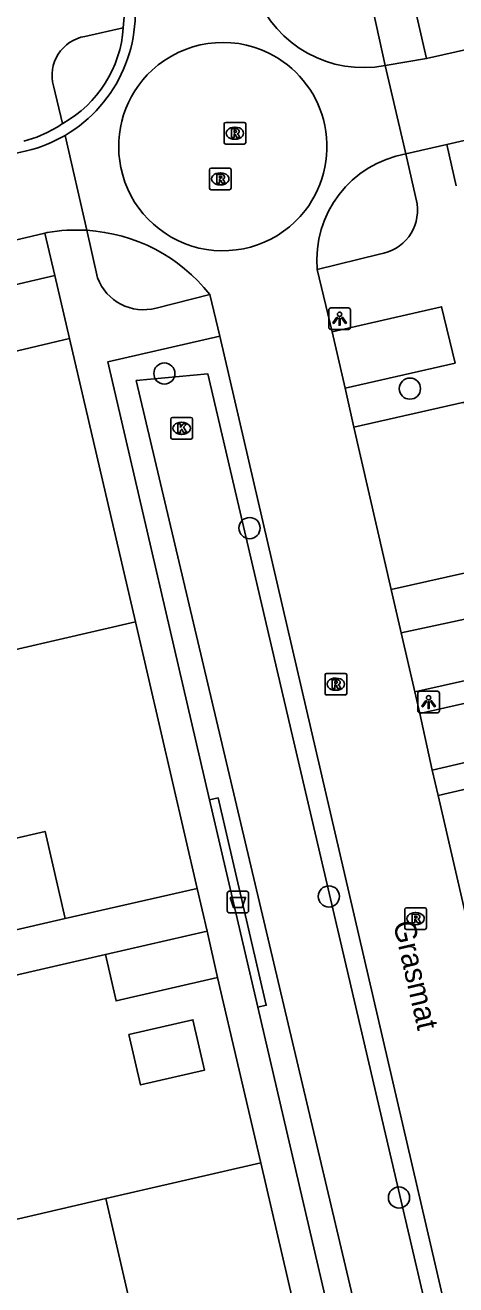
# Model space of a CAD drawing. Extents: x 156414 to 157775, y 382335 to 383765.
# Drawn here: x 156925.8 to 156945.6, y 382800.7 to 382858.9 of the extents above; entities that cross this region are included whole.
import ezdxf

# ---------------------------------------------------------------- set-up
doc = ezdxf.new("R2010")
doc.units = 0
for name, color, linetype in [('IMGEO_Afvalbak', 7, 'Continuous'), ('IMGEO_Boom', 7, 'Continuous'), ('IMGEO_Greppel_droge_sloot', 7, 'Continuous'), ('IMGEO_Haag', 7, 'Continuous'), ('IMGEO_Kolk', 7, 'Continuous'), ('IMGEO_Lichtpunt', 7, 'Continuous'), ('IMGEO_Muur', 7, 'Continuous'), ('IMGEO_Openbare_ruimte_label', 7, 'Continuous'), ('IMGEO_Pand', 7, 'Continuous'), ('IMGEO_Rijbaan_lokaal_gesloten', 7, 'Continuous'), ('IMGEO_Rijbaan_lokaal_open', 7, 'Continuous'), ('IMGEO_Rioolput', 7, 'Continuous'), ('IMGEO_Voetpad_open', 7, 'Continuous')]:
    doc.layers.add(name, color=color, linetype=linetype)

msp = doc.modelspace()

# ---------------------------------------------------------------- linework, layer by layer
at = {"layer": 'IMGEO_Afvalbak'}
for p, q in [((156935.078, 382817.947), (156935.078, 382818.747)), ((156935.078, 382818.747), (156935.078, 382817.947)), ((156935.178, 382818.847), (156935.968, 382818.847)), ((156935.968, 382818.847), (156935.178, 382818.847)), ((156936.068, 382818.747), (156936.068, 382817.947)), ((156936.068, 382817.947), (156936.068, 382818.747)), ((156935.968, 382817.847), (156935.178, 382817.847)), ((156935.178, 382817.847), (156935.968, 382817.847))]:
    msp.add_line(p, q, dxfattribs=at)
msp.add_lwpolyline([(156935.221, 382818.561), (156935.925, 382818.561), (156935.776, 382818.091), (156935.37, 382818.091), (156935.221, 382818.561)], dxfattribs=at)
for centre, start, end in [((156935.178, 382818.747), 90, 180), ((156935.178, 382818.747), 90, 180), ((156935.968, 382818.747), 0, 90), ((156935.968, 382818.747), 360, 90), ((156935.178, 382817.947), 180, 270), ((156935.178, 382817.947), 180, 270), ((156935.968, 382817.947), 270, 0), ((156935.968, 382817.947), 270, 0)]:
    msp.add_arc(centre, 0.1, start, end, dxfattribs=at)
at = {"layer": 'IMGEO_Boom'}
for centre in [(156932.178, 382842.779), (156943.519, 382842.081), (156936.113, 382835.634), (156939.776, 382818.609), (156943.014, 382804.691)]:
    msp.add_circle(centre, 0.489, dxfattribs=at)
at = {"layer": 'IMGEO_Greppel_droge_sloot'}
msp.add_lwpolyline([(156941.405, 382797.86), (156944.492, 382798.653), (156934.181, 382842.771), (156930.876, 382842.454), (156941.405, 382797.86)], dxfattribs=at)
at = {"layer": 'IMGEO_Haag'}
msp.add_lwpolyline([(156934.267, 382823.071), (156934.658, 382823.159), (156936.883, 382813.583), (156936.492, 382813.495)], dxfattribs=at)
at = {"layer": 'IMGEO_Kolk'}
for p, q in [((156932.55, 382840.748), (156933.402, 382840.748)), ((156932.475, 382839.822), (156932.475, 382840.674)), ((156932.963, 382840.528), (156932.988, 382840.528)), ((156933.476, 382840.674), (156933.476, 382839.822)), ((156933.402, 382839.748), (156932.55, 382839.748)), ((156932.986, 382839.968), (156932.961, 382839.968))]:
    msp.add_line(p, q, dxfattribs=at)
for points in [[(156932.55, 382840.748), (156933.402, 382840.748)], [(156932.475, 382839.822), (156932.475, 382840.674)], [(156932.796, 382840.448), (156932.919, 382840.448), (156932.919, 382840.297), (156933.049, 382840.448), (156933.213, 382840.448), (156933.067, 382840.297), (156933.22, 382840.048), (156933.068, 382840.048), (156932.983, 382840.212), (156932.919, 382840.145), (156932.919, 382840.048), (156932.796, 382840.048), (156932.796, 382840.448)], [(156933.476, 382840.674), (156933.476, 382839.822)], [(156933.402, 382839.748), (156932.55, 382839.748)]]:
    msp.add_lwpolyline(points, dxfattribs=at)
for centre, start, end in [((156932.552, 382840.672), 91.55205, 178.44795), ((156932.552, 382840.672), 91.55205, 178.44795), ((156933.4, 382840.672), 1.55205, 88.44795), ((156933.4, 382840.672), 1.55205, 88.44795), ((156932.552, 382839.824), 181.55205, 268.44795), ((156932.552, 382839.824), 181.55205, 268.44795), ((156933.4, 382839.824), 271.55205, 358.44795), ((156933.4, 382839.824), 271.55205, 358.44795)]:
    msp.add_arc(centre, 0.0765, start, end, dxfattribs=at)
for centre, major_axis, ratio, start_param, end_param in [((156932.962, 382840.248), (-0.387, 0.002), 0.722429, 4.712389, 7.853982), ((156932.987, 382840.248), (-0.39, 0.002), 0.717154, 1.570796, 4.712389)]:
    msp.add_ellipse(centre, major_axis=major_axis, ratio=ratio, start_param=start_param, end_param=end_param, dxfattribs=at)
at = {"layer": 'IMGEO_Lichtpunt'}
for p, q in [((156939.774, 382845.718), (156939.774, 382844.911)), ((156939.774, 382845.718), (156939.774, 382844.911)), ((156940.676, 382845.813), (156939.868, 382845.813)), ((156940.676, 382845.813), (156939.868, 382845.813)), ((156940.77, 382844.911), (156940.77, 382845.718)), ((156940.77, 382844.911), (156940.77, 382845.718)), ((156939.868, 382844.817), (156940.676, 382844.817)), ((156939.868, 382844.817), (156940.676, 382844.817)), ((156943.884, 382827.995), (156943.884, 382827.188)), ((156943.884, 382827.995), (156943.884, 382827.188)), ((156944.786, 382828.09), (156943.978, 382828.09)), ((156944.786, 382828.09), (156943.978, 382828.09)), ((156944.88, 382827.188), (156944.88, 382827.995)), ((156944.88, 382827.188), (156944.88, 382827.995)), ((156943.978, 382827.094), (156944.786, 382827.094)), ((156943.978, 382827.094), (156944.786, 382827.094))]:
    msp.add_line(p, q, dxfattribs=at)
for points in [[(156940.148, 382845.382), (156940.187, 382845.354), (156939.999, 382845.092), (156939.961, 382845.119), (156940.148, 382845.382)], [(156940.36, 382845.354), (156940.398, 382845.381), (156940.585, 382845.119), (156940.546, 382845.091), (156940.36, 382845.354)], [(156940.25, 382845.334), (156940.297, 382845.334), (156940.297, 382845.012), (156940.25, 382845.012), (156940.25, 382845.334)], [(156944.258, 382827.659), (156944.297, 382827.631), (156944.109, 382827.369), (156944.071, 382827.396), (156944.258, 382827.659)], [(156944.36, 382827.611), (156944.407, 382827.611), (156944.407, 382827.289), (156944.36, 382827.289), (156944.36, 382827.611)], [(156944.47, 382827.631), (156944.508, 382827.658), (156944.695, 382827.396), (156944.656, 382827.368), (156944.47, 382827.631)]]:
    msp.add_lwpolyline(points, dxfattribs=at)
for centre in [(156940.273, 382845.516), (156944.383, 382827.793)]:
    msp.add_circle(centre, 0.0994, dxfattribs=at)
for centre, start, end in [((156939.868, 382845.718), 90, 180), ((156939.868, 382845.718), 90, 180), ((156940.676, 382845.718), 0, 90), ((156940.676, 382845.718), 0, 90), ((156939.868, 382844.911), 180, 270), ((156939.868, 382844.911), 180, 270), ((156940.676, 382844.911), 270, 0), ((156940.676, 382844.911), 270, 360), ((156943.978, 382827.995), 90, 180), ((156943.978, 382827.995), 90, 180), ((156944.786, 382827.995), 0, 90), ((156944.786, 382827.995), 0, 90), ((156943.978, 382827.188), 180, 270), ((156943.978, 382827.188), 180, 270), ((156944.786, 382827.188), 270, 0), ((156944.786, 382827.188), 270, 360)]:
    msp.add_arc(centre, 0.0946, start, end, dxfattribs=at)
at = {"layer": 'IMGEO_Muur'}
for points in [[(156930.84, 382831.306), (156933.697, 382818.983)], [(156934.638, 382814.868), (156936.631, 382806.293)]]:
    msp.add_lwpolyline(points, dxfattribs=at)
at = {"layer": 'IMGEO_Pand'}
for points in [[(156927.788, 382844.392), (156924.464, 382843.616), (156924.664, 382842.759), (156922.103, 382842.162), (156922.58, 382840.117), (156920.242, 382839.571), (156919.736, 382839.453), (156919.531, 382839.405)], [(156927.788, 382844.392), (156930.84, 382831.306)], [(156930.84, 382831.306), (156921.915, 382829.231)], [(156924.725, 382816.92), (156923.79, 382820.948), (156926.665, 382821.615), (156927.6, 382817.588)], [(156927.6, 382817.588), (156924.725, 382816.92)], [(156929.454, 382815.919), (156934.158, 382817.006)], [(156934.158, 382817.006), (156934.638, 382814.868)], [(156934.638, 382814.868), (156929.95, 382813.781), (156929.454, 382815.919)], [(156930.537, 382812.225), (156931.078, 382809.895), (156934.035, 382810.581), (156933.494, 382812.911), (156930.537, 382812.225)], [(156929.471, 382804.64), (156936.631, 382806.293)], [(156936.631, 382806.293), (156939.348, 382794.6)], [(156922.45, 382803.019), (156929.471, 382804.64)], [(156931.509, 382795.84), (156929.471, 382804.64)]]:
    msp.add_lwpolyline(points, dxfattribs=at)
at = {"layer": 'IMGEO_Rijbaan_lokaal_gesloten'}
for points in [[(156981.73, 382861.789), (156980.19, 382861.433), (156978.786, 382861.108), (156976.761, 382860.639), (156945.223, 382853.37)], [(156949.295, 382858.468), (156944.29, 382857.344)], [(156944.29, 382857.344), (156942.376, 382857.01)], [(156942.376, 382857.01), (156943.33, 382852.932)], [(156927.595, 382853.788), (156928.589, 382849.398)], [(156704.67, 382802.003), (156706.623, 382802.451), (156776.982, 382818.697), (156816.178, 382827.739), (156855.39, 382836.785), (156925.817, 382853.068)], [(156943.33, 382852.932), (156945.223, 382853.37)], [(156926.664, 382849.268), (156923.197, 382848.454), (156856.378, 382832.904), (156817.084, 382823.811), (156780.281, 382815.295), (156707.464, 382798.538)], [(156926.769, 382849.293), (156926.664, 382849.268)], [(156939.242, 382847.585), (156939.925, 382844.701)], [(156934.272, 382846.434), (156934.733, 382844.509)], [(156934.733, 382844.509), (156945.614, 382797.617)], [(156940.529, 382842.099), (156939.925, 382844.701)], [(156940.529, 382842.099), (156940.931, 382840.306)], [(156942.646, 382832.797), (156940.931, 382840.306)], [(156942.646, 382832.797), (156943.112, 382830.796)], [(156943.748, 382828.064), (156943.112, 382830.796)], [(156943.748, 382828.064), (156943.982, 382827.057)], [(156944.552, 382824.438), (156943.982, 382827.057)], [(156944.552, 382824.438), (156944.82, 382823.277)], [(156947.139, 382813.241), (156944.82, 382823.277)]]:
    msp.add_lwpolyline(points, dxfattribs=at)
for centre, radius, start, end in [((156924.27, 382859.444), 6.561, 300.45331, 12.82908), ((156941.38, 382862.266), 5.349, 201.37835, 280.7259), ((156924.253, 382859.485), 6.605, 283.69623, 300.39468), ((156944.202, 382848.029), 4.98, 100.08144, 185.11978), ((156928.124, 382841.632), 7.78, 86.57326, 100.03047), ((156928.132, 382841.591), 7.82, 38.26383, 86.64709)]:
    msp.add_arc(centre, radius, start, end, dxfattribs=at)
at = {"layer": 'IMGEO_Rijbaan_lokaal_open'}
for points in [[(156930.281, 382858.756), (156930.325, 382859.272), (156930.326, 382859.696), (156930.273, 382860.291), (156930.181, 382860.808)], [(156925.683, 382853.514), (156926.283, 382853.698), (156926.76, 382853.92), (156927.263, 382854.185), (156927.472, 382854.33)], [(156927.49, 382854.34), (156927.472, 382854.33)]]:
    msp.add_lwpolyline(points, dxfattribs=at)
for centre, radius, start, end in [((156924.798, 382859.131), 5.495, 299.32659, 356.086), ((156934.877, 382853.275), 4.808, 63.80121, 132.74186), ((156934.879, 382853.275), 4.807, 15.00726, 63.81715), ((156934.876, 382853.274), 4.808, 132.72151, 191.76242), ((156934.886, 382853.26), 4.804, 322.0844, 15.20158), ((156934.879, 382853.26), 4.808, 191.58881, 256.73649), ((156934.88, 382853.26), 4.808, 256.72219, 322.12852)]:
    msp.add_arc(centre, radius, start, end, dxfattribs=at)
at = {"layer": 'IMGEO_Rioolput'}
for p, q in [((156934.934, 382853.461), (156934.934, 382854.313)), ((156935.009, 382854.387), (156935.861, 382854.387)), ((156935.422, 382854.167), (156935.447, 382854.167)), ((156935.935, 382854.313), (156935.935, 382853.461)), ((156935.445, 382853.607), (156935.42, 382853.607)), ((156935.861, 382853.387), (156935.009, 382853.387)), ((156934.26, 382851.348), (156934.26, 382852.2)), ((156934.335, 382852.274), (156935.187, 382852.274)), ((156934.748, 382852.054), (156934.773, 382852.054)), ((156935.261, 382852.2), (156935.261, 382851.348)), ((156935.187, 382851.274), (156934.335, 382851.274)), ((156934.771, 382851.494), (156934.746, 382851.494)), ((156939.597, 382827.994), (156939.597, 382828.846)), ((156939.672, 382828.92), (156940.524, 382828.92)), ((156940.085, 382828.7), (156940.11, 382828.7)), ((156940.598, 382828.846), (156940.598, 382827.994)), ((156940.524, 382827.92), (156939.672, 382827.92)), ((156940.108, 382828.14), (156940.083, 382828.14)), ((156943.281, 382817.157), (156943.281, 382818.009)), ((156943.356, 382818.083), (156944.208, 382818.083)), ((156944.282, 382818.009), (156944.282, 382817.157)), ((156943.769, 382817.863), (156943.794, 382817.863)), ((156944.208, 382817.083), (156943.356, 382817.083)), ((156943.792, 382817.303), (156943.767, 382817.303))]:
    msp.add_line(p, q, dxfattribs=at)
for points in [[(156934.934, 382853.461), (156934.934, 382854.313)], [(156935.009, 382854.387), (156935.861, 382854.387)], [(156935.523, 382854.085), (156935.271, 382854.087), (156935.271, 382853.687)], [(156935.935, 382854.313), (156935.935, 382853.461)], [(156935.271, 382853.687), (156935.395, 382853.687), (156935.395, 382853.849), (156935.406, 382853.849)], [(156935.449, 382854.006), (156935.395, 382854.006), (156935.395, 382853.925)], [(156935.395, 382853.925), (156935.447, 382853.925)], [(156935.453, 382853.82), (156935.524, 382853.687), (156935.664, 382853.687), (156935.599, 382853.813)], [(156935.861, 382853.387), (156935.009, 382853.387)], [(156934.26, 382851.348), (156934.26, 382852.2)], [(156934.335, 382852.274), (156935.187, 382852.274)], [(156934.849, 382851.972), (156934.597, 382851.974), (156934.597, 382851.574)], [(156934.775, 382851.893), (156934.721, 382851.893), (156934.721, 382851.812)], [(156934.721, 382851.812), (156934.773, 382851.812)], [(156935.261, 382852.2), (156935.261, 382851.348)], [(156935.187, 382851.274), (156934.335, 382851.274)], [(156934.597, 382851.574), (156934.721, 382851.574), (156934.721, 382851.736), (156934.732, 382851.736)], [(156934.779, 382851.707), (156934.85, 382851.574), (156934.99, 382851.574), (156934.925, 382851.7)], [(156939.597, 382827.994), (156939.597, 382828.846)], [(156939.672, 382828.92), (156940.524, 382828.92)], [(156940.186, 382828.618), (156939.934, 382828.62), (156939.934, 382828.22)], [(156940.112, 382828.539), (156940.058, 382828.539), (156940.058, 382828.458)], [(156940.598, 382828.846), (156940.598, 382827.994)], [(156940.524, 382827.92), (156939.672, 382827.92)], [(156939.934, 382828.22), (156940.058, 382828.22), (156940.058, 382828.382), (156940.069, 382828.382)], [(156940.058, 382828.458), (156940.11, 382828.458)], [(156940.116, 382828.353), (156940.187, 382828.22), (156940.327, 382828.22), (156940.262, 382828.346)], [(156943.281, 382817.157), (156943.281, 382818.009)], [(156943.356, 382818.083), (156944.208, 382818.083)], [(156944.282, 382818.009), (156944.282, 382817.157)], [(156943.87, 382817.781), (156943.618, 382817.783), (156943.618, 382817.383)], [(156943.618, 382817.383), (156943.742, 382817.383), (156943.742, 382817.545), (156943.753, 382817.545)], [(156943.796, 382817.702), (156943.742, 382817.702), (156943.742, 382817.621)], [(156943.742, 382817.621), (156943.794, 382817.621)], [(156943.8, 382817.516), (156943.871, 382817.383), (156944.011, 382817.383), (156943.946, 382817.509)], [(156944.208, 382817.083), (156943.356, 382817.083)]]:
    msp.add_lwpolyline(points, dxfattribs=at)
for centre, radius, start, end in [((156935.011, 382854.311), 0.0765, 91.55205, 178.44795), ((156935.011, 382854.311), 0.0765, 91.55205, 178.44795), ((156935.522, 382853.975), 0.109, 350.36119, 89.41601), ((156935.859, 382854.311), 0.0765, 1.55205, 88.44795), ((156935.859, 382854.311), 0.0765, 1.55205, 88.44795), ((156935.405, 382853.796), 0.0533, 26.02933, 88.69889), ((156935.431, 382854.114), 0.19, 274.7715, 282.96867), ((156935.455, 382853.91), 0.0964, 77.00612, 93.18647), ((156935.469, 382853.967), 0.0378, 276.66336, 79.67722), ((156935.52, 382853.975), 0.112, 277.58423, 350.98172), ((156935.504, 382853.76), 0.108, 29.51342, 73.79051), ((156935.011, 382853.463), 0.0765, 181.55205, 268.44795), ((156935.011, 382853.463), 0.0765, 181.55205, 268.44795), ((156935.859, 382853.463), 0.0765, 271.55205, 358.44795), ((156935.859, 382853.463), 0.0765, 271.55205, 358.44795), ((156934.337, 382852.198), 0.0765, 91.55205, 178.44795), ((156934.337, 382852.198), 0.0765, 91.55205, 178.44795), ((156934.757, 382852.001), 0.19, 274.7715, 282.96867), ((156934.781, 382851.797), 0.0964, 77.00612, 93.18647), ((156934.795, 382851.854), 0.0378, 276.66336, 79.67722), ((156934.848, 382851.862), 0.109, 350.36119, 89.41601), ((156934.846, 382851.862), 0.112, 277.58423, 350.98172), ((156935.185, 382852.198), 0.0765, 1.55205, 88.44795), ((156935.185, 382852.198), 0.0765, 1.55205, 88.44795), ((156934.337, 382851.35), 0.0765, 181.55205, 268.44795), ((156934.337, 382851.35), 0.0765, 181.55205, 268.44795), ((156934.731, 382851.683), 0.0533, 26.02933, 88.69889), ((156934.83, 382851.647), 0.108, 29.51342, 73.79051), ((156935.185, 382851.35), 0.0765, 271.55205, 358.44795), ((156935.185, 382851.35), 0.0765, 271.55205, 358.44795), ((156939.674, 382828.844), 0.0765, 91.55205, 178.44795), ((156939.674, 382828.844), 0.0765, 91.55205, 178.44795), ((156940.118, 382828.443), 0.0964, 77.00612, 93.18647), ((156940.132, 382828.5), 0.0378, 276.66336, 79.67722), ((156940.185, 382828.508), 0.109, 350.36119, 89.41601), ((156940.183, 382828.508), 0.112, 277.58423, 350.98172), ((156940.522, 382828.844), 0.0765, 1.55205, 88.44795), ((156940.522, 382828.844), 0.0765, 1.55205, 88.44795), ((156939.674, 382827.996), 0.0765, 181.55205, 268.44795), ((156939.674, 382827.996), 0.0765, 181.55205, 268.44795), ((156940.068, 382828.329), 0.0533, 26.02933, 88.69889), ((156940.094, 382828.647), 0.19, 274.7715, 282.96867), ((156940.167, 382828.293), 0.108, 29.51342, 73.79051), ((156940.522, 382827.996), 0.0765, 271.55205, 358.44795), ((156940.522, 382827.996), 0.0765, 271.55205, 358.44795), ((156943.358, 382818.007), 0.0765, 91.55205, 178.44795), ((156943.358, 382818.007), 0.0765, 91.55205, 178.44795), ((156944.206, 382818.007), 0.0765, 1.55205, 88.44795), ((156944.206, 382818.007), 0.0765, 1.55205, 88.44795), ((156943.752, 382817.492), 0.0533, 26.02933, 88.69889), ((156943.778, 382817.81), 0.19, 274.7715, 282.96867), ((156943.802, 382817.606), 0.0964, 77.00612, 93.18647), ((156943.816, 382817.663), 0.0378, 276.66336, 79.67722), ((156943.869, 382817.671), 0.109, 350.36119, 89.41601), ((156943.867, 382817.671), 0.112, 277.58423, 350.98172), ((156943.851, 382817.456), 0.108, 29.51342, 73.79051), ((156943.358, 382817.159), 0.0765, 181.55205, 268.44795), ((156943.358, 382817.159), 0.0765, 181.55205, 268.44795), ((156944.206, 382817.159), 0.0765, 271.55205, 358.44795), ((156944.206, 382817.159), 0.0765, 271.55205, 358.44795)]:
    msp.add_arc(centre, radius, start, end, dxfattribs=at)
for centre, major_axis, ratio, start_param, end_param in [((156935.421, 382853.887), (-0.387, 0.002), 0.722429, 4.712389, 7.853982), ((156935.446, 382853.887), (-0.39, 0.002), 0.717154, 1.570796, 4.712389), ((156934.747, 382851.774), (-0.387, 0.002), 0.722429, 4.712389, 7.853982), ((156934.772, 382851.774), (-0.39, 0.002), 0.717154, 1.570796, 4.712389), ((156940.084, 382828.42), (-0.387, 0.002), 0.722429, 4.712389, 7.853982), ((156940.109, 382828.42), (-0.39, 0.002), 0.717154, 1.570796, 4.712389), ((156943.768, 382817.583), (-0.387, 0.002), 0.722429, 4.712389, 7.853982), ((156943.793, 382817.583), (-0.39, 0.002), 0.717154, 1.570796, 4.712389)]:
    msp.add_ellipse(centre, major_axis=major_axis, ratio=ratio, start_param=start_param, end_param=end_param, dxfattribs=at)
at = {"layer": 'IMGEO_Voetpad_open'}
for points in [[(156944.66, 382862.523), (156943.175, 382862.185), (156944.29, 382857.344)], [(156942.376, 382857.01), (156941.829, 382859.538)], [(156928.499, 382858.363), (156930.281, 382858.756)], [(156927.472, 382854.33), (156927.051, 382856.077)], [(156943.33, 382852.932), (156943.852, 382850.616)], [(156945.223, 382853.37), (156945.662, 382851.459)], [(156926.664, 382849.268), (156927.114, 382847.315)], [(156929.096, 382847.209), (156928.589, 382849.398)], [(156942.115, 382848.3), (156939.242, 382847.585)], [(156856.714, 382830.844), (156856.91, 382830.891), (156859.126, 382831.425), (156927.114, 382847.315)], [(156927.114, 382847.315), (156927.788, 382844.392)], [(156934.272, 382846.434), (156931.795, 382845.803)], [(156939.925, 382844.701), (156944.981, 382845.863), (156945.604, 382843.264), (156940.529, 382842.099)], [(156934.267, 382823.071), (156929.564, 382843.312), (156934.733, 382844.509)], [(156940.931, 382840.306), (156946.021, 382841.454), (156947.737, 382833.938), (156942.646, 382832.797)], [(156943.112, 382830.796), (156948.214, 382831.89), (156948.839, 382829.202), (156943.748, 382828.064)], [(156933.697, 382818.983), (156930.84, 382831.306)], [(156943.982, 382827.057), (156949.069, 382828.214), (156949.694, 382825.649), (156944.552, 382824.438)], [(156944.82, 382823.277), (156949.979, 382824.473), (156952.261, 382814.432), (156947.139, 382813.241)], [(156936.492, 382813.495), (156934.267, 382823.071)], [(156933.697, 382818.983), (156927.6, 382817.588)], [(156934.158, 382817.006), (156933.697, 382818.983)], [(156924.651, 382814.81), (156929.454, 382815.919)], [(156934.638, 382814.868), (156936.631, 382806.293)], [(156940.464, 382796.399), (156936.492, 382813.495)]]:
    msp.add_lwpolyline(points, dxfattribs=at)
for centre, radius, start, end in [((156928.831, 382856.551), 1.842, 100.38447, 194.91349), ((156941.824, 382850.328), 2.048, 278.1689, 8.09131), ((156931.212, 382847.978), 2.252, 199.96783, 284.99912)]:
    msp.add_arc(centre, radius, start, end, dxfattribs=at)

# ---------------------------------------------------------------- texts
at = {"layer": 'IMGEO_Openbare_ruimte_label'}
msp.add_text('Grasmat', height=1, rotation=282.93881, dxfattribs=at).set_placement((156942.738, 382817.37))

doc.saveas('drawing.dxf')
